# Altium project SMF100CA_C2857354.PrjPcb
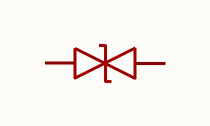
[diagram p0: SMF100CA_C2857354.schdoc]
1 sheet, 1 parts. Net scope: global (net labels, ports and power ports of the same name join across sheets).

## Sheet SMF100CA_C2857354.schdoc
size 127 x 101 mm

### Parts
D?  smf100ca_c2857354  [SOD-123FL_L2.8-W1.8-LS3.7-BI]  (value not drawn)

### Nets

Not connected (* = marked no-connect by the designer): D? 1 2

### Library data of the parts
D? = smf100ca_c2857354: 极性:双向;反向截止电压(Vrwm):100V;钳位电压:162V;峰值脉冲电流(Ipp):1.2A;峰值脉冲功率(Ppp):200W@10/1000us;击穿电压(VBR):111V;; Manufacturer: JSMSEMI(杰盛微); AddInBom: yes; ModelId: d105299b3871451c86f679efef28ff8f; ModelTransform: 145.669,70.866,0,0,0,0,0,0,0; Polarity: 双向; Reverse Stand-Off Voltage (Vrwm): 100V; Clamping Voltage: 162V; Peak Pulse Current (Ipp): 1.2A; Voltage - Breakdown: 111V; Reverse Leakage Current (Ir): 1uA; Number of Channels: 单路; Type: TVS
